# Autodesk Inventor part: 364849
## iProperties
Company: Hundt & Weber AG Schaltgeräte
Created: 2005-12
Part Number: 364849
Material: 1.0718.07
Description: Kern
Document SubType Name: Modeling
Designer: I.Baliuc
Manufacturer: Standard
Standards Organization: Custom
Density: 7.84 g/cm^3
HalbzeugNorm: DIN 178
Zweck: für Blasspule / DC-Schalter
Abmessung: 40x40-41
Author: I.Baliuc
Keywords: 380158
Revision Number: 364849
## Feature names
1. Extrusion2
2. Drehung1 [Revolution]
